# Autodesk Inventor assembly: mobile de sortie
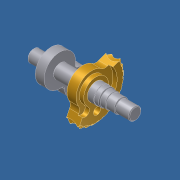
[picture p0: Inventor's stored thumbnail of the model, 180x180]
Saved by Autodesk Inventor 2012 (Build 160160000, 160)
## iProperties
Created: 2011-10
Part Number: mobile de sortie
Document SubType Name: Assembly
Designer: Laur
Author: Laur
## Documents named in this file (5)
- D:\Formulaire\Sujet CIM 2012\Modélisation_7970_shimano\mobile de sortie.iam
- D:\Formulaire\Sujet CIM 2012\Modélisation_7970_shimano\arbre de sortie.ipt
- D:\Formulaire\Sujet CIM 2012\Modélisation_7970_shimano\secteur de roue de vis sans fin.ipt
- D:\Formulaire\Sujet CIM 2012\Modélisation_7970_shimano\maneton.ipt
- D:\Formulaire\Sujet CIM 2012\Modélisation_7970_shimano\manivelle.ipt
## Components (4 placed, 4 different names)
1. arbre de sortie:1 — montage manivelle / arbre de sortie, montage secteur denté
2. secteur de roue de vis sans fin:1 — montage secteur denté, pos angulaire relative manivelle / secteur denté
3. maneton:1 — montage maneton / manivelle
4. manivelle:1 — montage maneton / manivelle, montage manivelle / arbre de sortie, pos angulaire relative manivelle / secteur denté
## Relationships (4: Insert 3, Angle 1)
- montage maneton / manivelle [Insert]: maneton:1 ↔ manivelle:1
- montage manivelle / arbre de sortie [Insert]: arbre de sortie:1 ↔ manivelle:1
- montage secteur denté [Insert]: arbre de sortie:1 ↔ secteur de roue de vis sans fin:1
- pos angulaire relative manivelle / secteur denté [Angle]: secteur de roue de vis sans fin:1 ↔ manivelle:1
